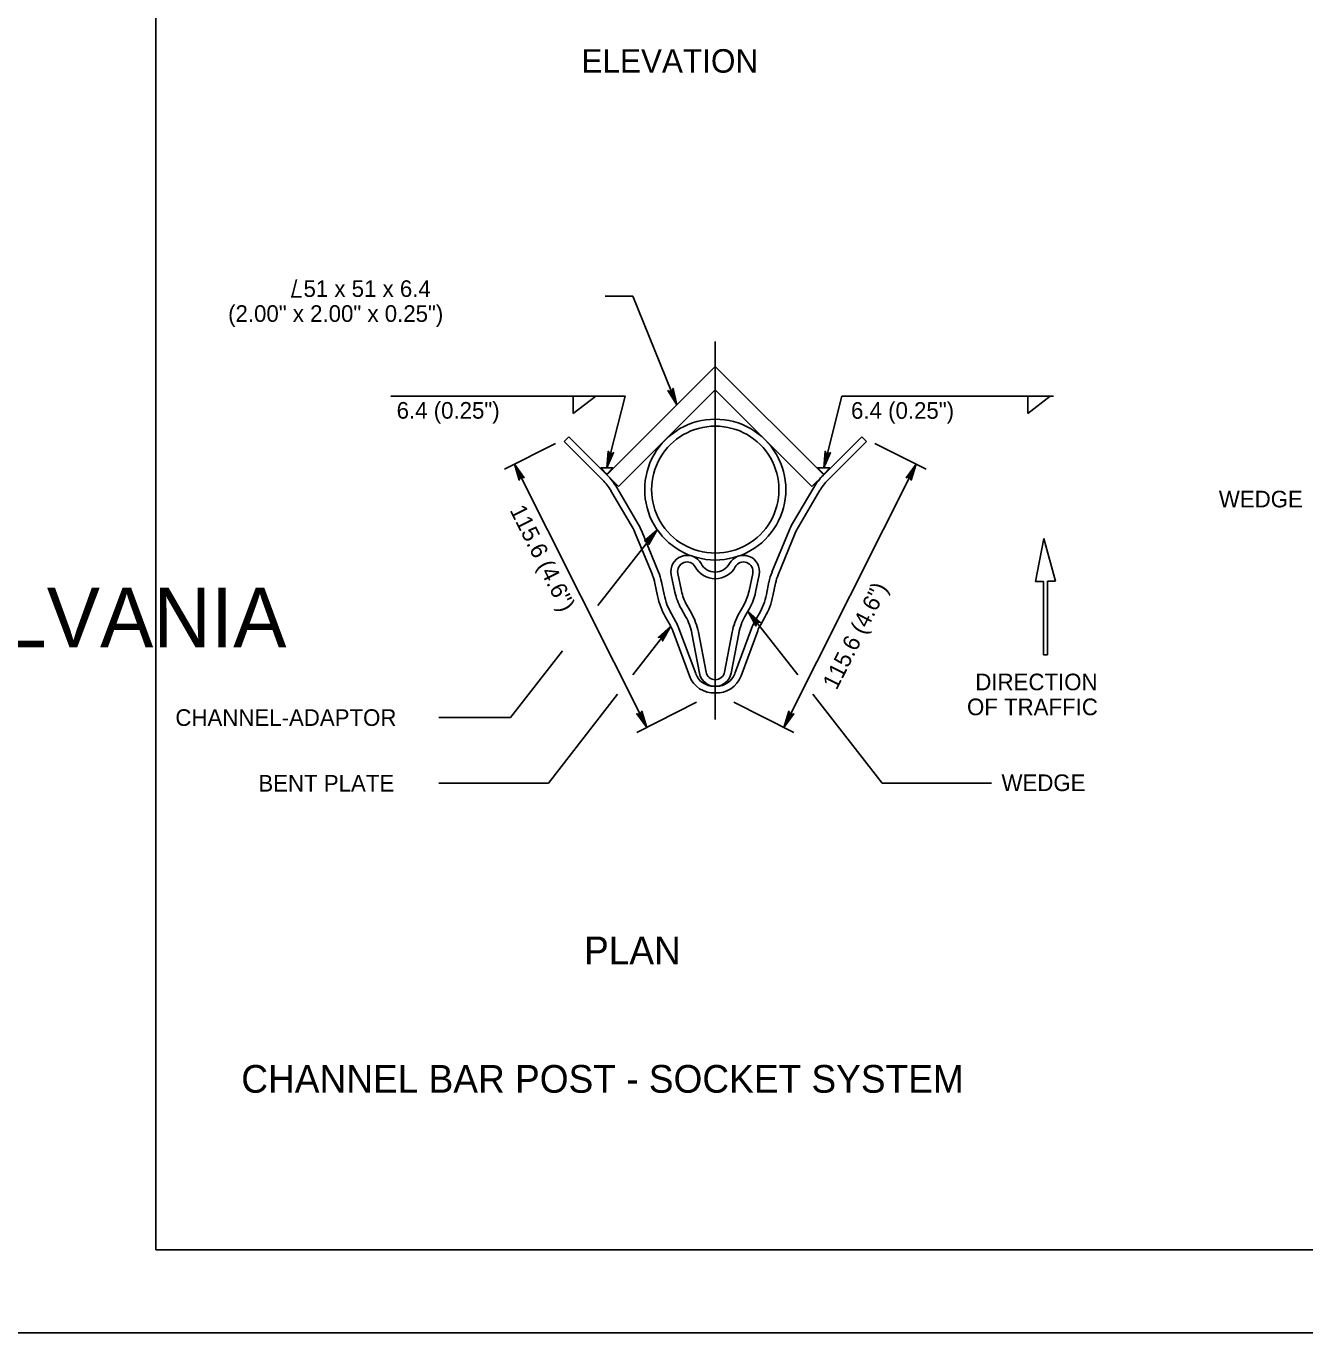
# Model space of a CAD drawing. Extents: x 644358 to 648627, y 294594 to 295782.
# Drawn here: x 646056.9 to 646287.7, y 294593.6 to 294829.5 of the extents above; entities that cross this region are included whole.
import ezdxf

# ---------------------------------------------------------------- set-up
doc = ezdxf.new("R2010")
doc.units = 0
for name, color, linetype in [('1', 7, 'Continuous'), ('2', 7, 'Continuous'), ('3', 7, 'Continuous'), ('4', 7, 'Continuous'), ('PLT-BNDY', 7, 'Continuous')]:
    doc.layers.add(name, color=color, linetype=linetype)

# ---------------------------------------------------------------- blocks, each defined once
blk = doc.blocks.new('RARROW')
at = {"layer": '3'}
blk.add_lwpolyline([(-2.2695, 0.285), (-2.184875, 0.12075), (0, 0), (-2.2695, 0.285), (-2.38575, 0.384625), (0, 0), (-2.183125, -0.108), (-2.262875, -0.2705), (0, 0), (-2.38575, -0.379125), (-2.262875, -0.2705)], dxfattribs=at)

msp = doc.modelspace()

# ---------------------------------------------------------------- linework, layer by layer
at = {"layer": '1'}
for p, q in [((646080.31, 295172.63), (646080.31, 294608.63)), ((646181.28, 294772.58), (646181.28, 294704.35)), ((646181.28, 294772.58), (646181.28, 294704.35)), ((646181.04, 294710.32), (646181.28, 294710.32)), ((646181.52, 294710.32), (646181.28, 294710.32)), ((646866.31, 294608.63), (646080.31, 294608.63)), ((646080.31, 294608.63), (646666.31, 294608.63))]:
    msp.add_line(p, q, dxfattribs=at)
at = {"layer": '2'}
for p, q in [((646106.59, 294780.62), (646104.75, 294780.62)), ((646161.43, 294780.71), (646166.43, 294780.71)), ((646166.43, 294780.71), (646174.34, 294761.12)), ((646122.75, 294762.67), (646165, 294762.67)), ((646155.65, 294759.56), (646155.65, 294762.67)), ((646159.71, 294762.67), (646155.65, 294759.56)), ((646161.71, 294749.73), (646165, 294762.67)), ((646200.85, 294749.73), (646204.13, 294762.67)), ((646204.13, 294762.67), (646242.36, 294762.67)), ((646237.68, 294759.55), (646237.68, 294762.67)), ((646241.75, 294762.67), (646237.68, 294759.55)), ((646152.45, 294754.17), (646143.23, 294749.54)), ((646210.11, 294754.17), (646219.33, 294749.54)), ((646168.91, 294702.91), (646145.02, 294750.44)), ((646193.65, 294702.91), (646217.54, 294750.44)), ((646160.62, 294749.73), (646162.81, 294749.73)), ((646161.71, 294748.63), (646160.62, 294749.73)), ((646162.81, 294749.73), (646161.71, 294748.63)), ((646199.75, 294749.73), (646201.94, 294749.73)), ((646200.85, 294748.63), (646199.75, 294749.73)), ((646201.94, 294749.73), (646200.85, 294748.63)), ((646170.79, 294738.59), (646160.1, 294724.89)), ((646240.56, 294737.03), (646239.08, 294729.22)), ((646242.67, 294729.3), (646240.56, 294737.03)), ((646239.08, 294729.22), (646240.53, 294729.22)), ((646240.53, 294729.22), (646240.53, 294715.98)), ((646241.23, 294715.98), (646241.23, 294729.3)), ((646241.23, 294729.3), (646242.67, 294729.3)), ((646187.18, 294723.9), (646196.17, 294712.38)), ((646173.25, 294721.17), (646166.39, 294712.38)), ((646153.7, 294716.7), (646144.35, 294704.71)), ((646240.53, 294715.98), (646241.23, 294715.98)), ((646163.66, 294708.89), (646151.16, 294692.87)), ((646198.9, 294708.89), (646211.4, 294692.87)), ((646177.92, 294707.44), (646167.12, 294702.01)), ((646184.64, 294707.44), (646195.44, 294702.01)), ((646131.41, 294704.71), (646144.35, 294704.71)), ((646131.41, 294692.87), (646151.16, 294692.87)), ((646211.4, 294692.87), (646231.15, 294692.87))]:
    msp.add_line(p, q, dxfattribs=at)
for centre, radius, start, end in [((646203.86, 294734.64), 10, 149.5025, 157.6977), ((646203.86, 294734.64), 8.8, 149.5025, 157.6977), ((646167.23, 294717.99), 6.8, 20.3297, 29.5668)]:
    msp.add_arc(centre, radius, start, end, dxfattribs=at)
at = {"layer": '3'}
for p, q in [((646161.71, 294748.49), (646181.28, 294768.06)), ((646200.85, 294748.49), (646181.28, 294768.06)), ((646163.83, 294746.37), (646181.28, 294763.82)), ((646198.73, 294746.37), (646181.28, 294763.82)), ((646154.83, 294755.37), (646153.99, 294754.52)), ((646161.77, 294748.44), (646154.83, 294755.37)), ((646200.79, 294748.44), (646207.73, 294755.37)), ((646207.73, 294755.37), (646208.57, 294754.52)), ((646160.92, 294747.59), (646153.99, 294754.52)), ((646201.64, 294747.59), (646208.57, 294754.52)), ((646163.83, 294746.37), (646161.77, 294748.44)), ((646198.73, 294746.37), (646200.79, 294748.44)), ((646172.04, 294726.89), (646171.58, 294729.15)), ((646174, 294727.3), (646173.35, 294730.47)), ((646175.18, 294727.54), (646174.52, 294730.71)), ((646187.38, 294727.54), (646188.04, 294730.71)), ((646188.56, 294727.3), (646189.21, 294730.47)), ((646190.52, 294726.89), (646190.98, 294729.15)), ((646170.87, 294726.65), (646170.4, 294728.91)), ((646191.69, 294726.65), (646192.16, 294728.91)), ((646175.1, 294724.39), (646175.93, 294722.93)), ((646176.14, 294724.98), (646176.97, 294723.52)), ((646186.42, 294724.98), (646185.59, 294723.52)), ((646187.46, 294724.39), (646186.63, 294722.93)), ((646172.31, 294722.81), (646173.14, 294721.35)), ((646173.36, 294723.4), (646174.19, 294721.94)), ((646189.2, 294723.4), (646188.37, 294721.94)), ((646190.25, 294722.81), (646189.42, 294721.35)), ((646176.63, 294712.19), (646173.61, 294720.36)), ((646177.76, 294712.61), (646174.73, 294720.77)), ((646177.05, 294719.88), (646178.43, 294712.68)), ((646178.23, 294720.1), (646179.61, 294712.9)), ((646184.33, 294720.1), (646182.95, 294712.9)), ((646185.51, 294719.88), (646184.13, 294712.68)), ((646184.8, 294712.61), (646187.83, 294720.77)), ((646185.93, 294712.19), (646188.95, 294720.36))]:
    msp.add_line(p, q, dxfattribs=at)
for points in [[(646166.29, 294739.11), (646162.46, 294745.6)], [(646167.32, 294739.72), (646163.5, 294746.2)], [(646195.24, 294739.72), (646199.06, 294746.2)], [(646196.28, 294739.11), (646200.1, 294745.6)], [(646169.93, 294730.47), (646166.84, 294737.98)], [(646171.04, 294730.92), (646167.95, 294738.44)], [(646191.52, 294730.92), (646194.61, 294738.44)], [(646192.63, 294730.47), (646195.72, 294737.98)]]:
    msp.add_lwpolyline(points, dxfattribs=at)
for centre, radius, start, end in [((646181.24, 294745.82), 12.7, 89.8201, 270.1799), ((646181.32, 294745.82), 12.7, 269.8201, 90.1799), ((646181.24, 294745.82), 11.45, 89.8005, 270.1995), ((646181.32, 294745.82), 11.45, 269.8005, 90.1995), ((646153.85, 294740.52), 11.2, 30.4975, 45), ((646208.71, 294740.52), 11.2, 135, 149.5025), ((646153.85, 294740.52), 10, 30.4975, 45), ((646208.71, 294740.52), 10, 135, 149.5025), ((646158.7, 294734.64), 8.8, 22.3023, 30.4975), ((646158.7, 294734.64), 10, 22.3023, 30.4975), ((646176.19, 294731.06), 2.9, 29.3625, 191.685), ((646186.37, 294731.06), 2.9, 348.315, 150.6375), ((646176.19, 294731.06), 1.7, 29.3625, 191.685), ((646181.27, 294733.85), 4.1, 208.2172, 270.2227), ((646181.27, 294733.85), 2.9, 208.2172, 270.2227), ((646181.29, 294733.85), 2.9, 269.7773, 331.7828), ((646181.29, 294733.85), 4.1, 269.7773, 331.7828), ((646186.37, 294731.06), 1.7, 348.315, 150.6375), ((646161.78, 294727.13), 8.8, 11.6854, 22.3023), ((646161.78, 294727.13), 10, 11.6854, 22.3023), ((646200.78, 294727.13), 10, 157.6977, 168.3146), ((646200.78, 294727.13), 8.8, 157.6977, 168.3146), ((646183.8, 294729.32), 12, 191.6854, 209.5668), ((646183.8, 294729.32), 10, 191.6854, 209.5668), ((646183.8, 294729.32), 8.8, 191.6854, 209.5668), ((646178.76, 294729.32), 8.8, 330.4332, 348.3146), ((646178.76, 294729.32), 10, 330.4332, 348.3146), ((646178.76, 294729.32), 12, 330.4332, 348.3146), ((646183.8, 294729.32), 13.2, 191.6854, 209.5668), ((646178.76, 294729.32), 13.2, 330.4332, 348.3146), ((646167.23, 294717.99), 8, 20.3297, 29.5668), ((646167.23, 294717.99), 10, 10.8647, 29.5668), ((646167.23, 294717.99), 11.2, 10.8647, 29.5668), ((646195.33, 294717.99), 11.2, 150.4332, 169.1353), ((646195.33, 294717.99), 10, 150.4332, 169.1353), ((646195.33, 294717.99), 8, 150.4332, 159.6703), ((646195.33, 294717.99), 6.8, 150.4332, 159.6703), ((646181.04, 294713.82), 3.5, 200.3297, 270), ((646181.28, 294713.22), 2.9, 190.8647, 270), ((646181.28, 294713.22), 1.7, 190.8647, 270), ((646181.28, 294713.22), 1.7, 270, 349.1353), ((646181.28, 294713.22), 2.9, 270, 349.1353), ((646181.52, 294713.82), 3.5, 270, 339.6703), ((646181.04, 294713.82), 4.7, 200.3297, 272.9539), ((646181.52, 294713.82), 4.7, 267.0461, 339.6703)]:
    msp.add_arc(centre, radius, start, end, dxfattribs=at)
at = {"layer": 'PLT-BNDY'}
msp.add_lwpolyline([(646040.31, 295187.63), (646881.31, 295187.63), (646881.31, 294593.63), (646040.31, 294593.63)], close=True, dxfattribs=at)

# ---------------------------------------------------------------- block references
at = {"layer": '2'}
for p, xscale, yscale, rotation in [((646174.34, 294761.12), 1.2574347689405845, 1.3092961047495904, -67.59902542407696), ((646161.71, 294749.73), 1.2574347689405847, 1.3092961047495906, -104.19570215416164), ((646200.85, 294749.73), 1.2574347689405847, 1.3092961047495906, -104.19570215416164), ((646145.02, 294750.44), 1.2574347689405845, 1.3092961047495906, 116.56916879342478), ((646217.54, 294750.44), 1.2574347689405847, -1.3092961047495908, 63.43083120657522), ((646170.79, 294738.59), 1.2574347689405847, 1.3092961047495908, 51.43561221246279), ((646187.18, 294723.9), 1.2574347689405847, 1.3092961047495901, 128.03213898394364), ((646173.25, 294721.17), 1.2574347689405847, 1.3092961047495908, 51.43561221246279), ((646168.91, 294702.91), 1.2574347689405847, 1.3092961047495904, -63.277657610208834), ((646193.65, 294702.91), 1.257434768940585, -1.3092961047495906, -116.7223423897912)]:
    msp.add_blockref('RARROW', p, dxfattribs=dict(at, xscale=xscale, yscale=yscale, rotation=rotation))

# ---------------------------------------------------------------- texts
at = {"layer": '1'}
msp.add_text('COMMONWEALTH OF PENNSYLVANIA', height=10.7828, dxfattribs=at).set_placement((645837.9, 294717.36))
at = {"layer": '2'}
for s, height, p in [('/ 51 x 51 x 6.4', 3, (646104.73, 294780.6)), ('(2.00" x 2.00" x 0.25")', 3, (646093.35, 294776.1)), ('6.4 (0.25")', 3, (646123.77, 294758.63)), ('6.4 (0.25")', 3, (646205.79, 294758.61)), ('WEDGE', 3, (646272.18, 294742.62)), ('DIRECTION', 3, (646228.22, 294709.61)), ('OF TRAFFIC', 3, (646226.72, 294705.11)), ('CHANNEL-ADAPTOR', 3, (646083.83, 294703.18)), ('BENT PLATE', 3, (646098.81, 294691.32)), ('WEDGE', 3, (646232.95, 294691.42)), ('PLAN', 5, (646157.6, 294660.16)), ('CHANNEL BAR POST - SOCKET SYSTEM', 5, (646095.73, 294636.97))]:
    msp.add_text(s, height=height, dxfattribs=at).set_placement(p)
at = {"layer": '4'}
msp.add_text('ELEVATION', height=4.25, dxfattribs=at).set_placement((646157.13, 294821.07))
for rotation, p in [(296.6869, (646144.11, 294742.13)), (63.3131, (646203.19, 294709.51))]:
    msp.add_text('115.6 (4.6")', height=3, rotation=rotation, dxfattribs=at).set_placement(p)

doc.saveas('drawing.dxf')
